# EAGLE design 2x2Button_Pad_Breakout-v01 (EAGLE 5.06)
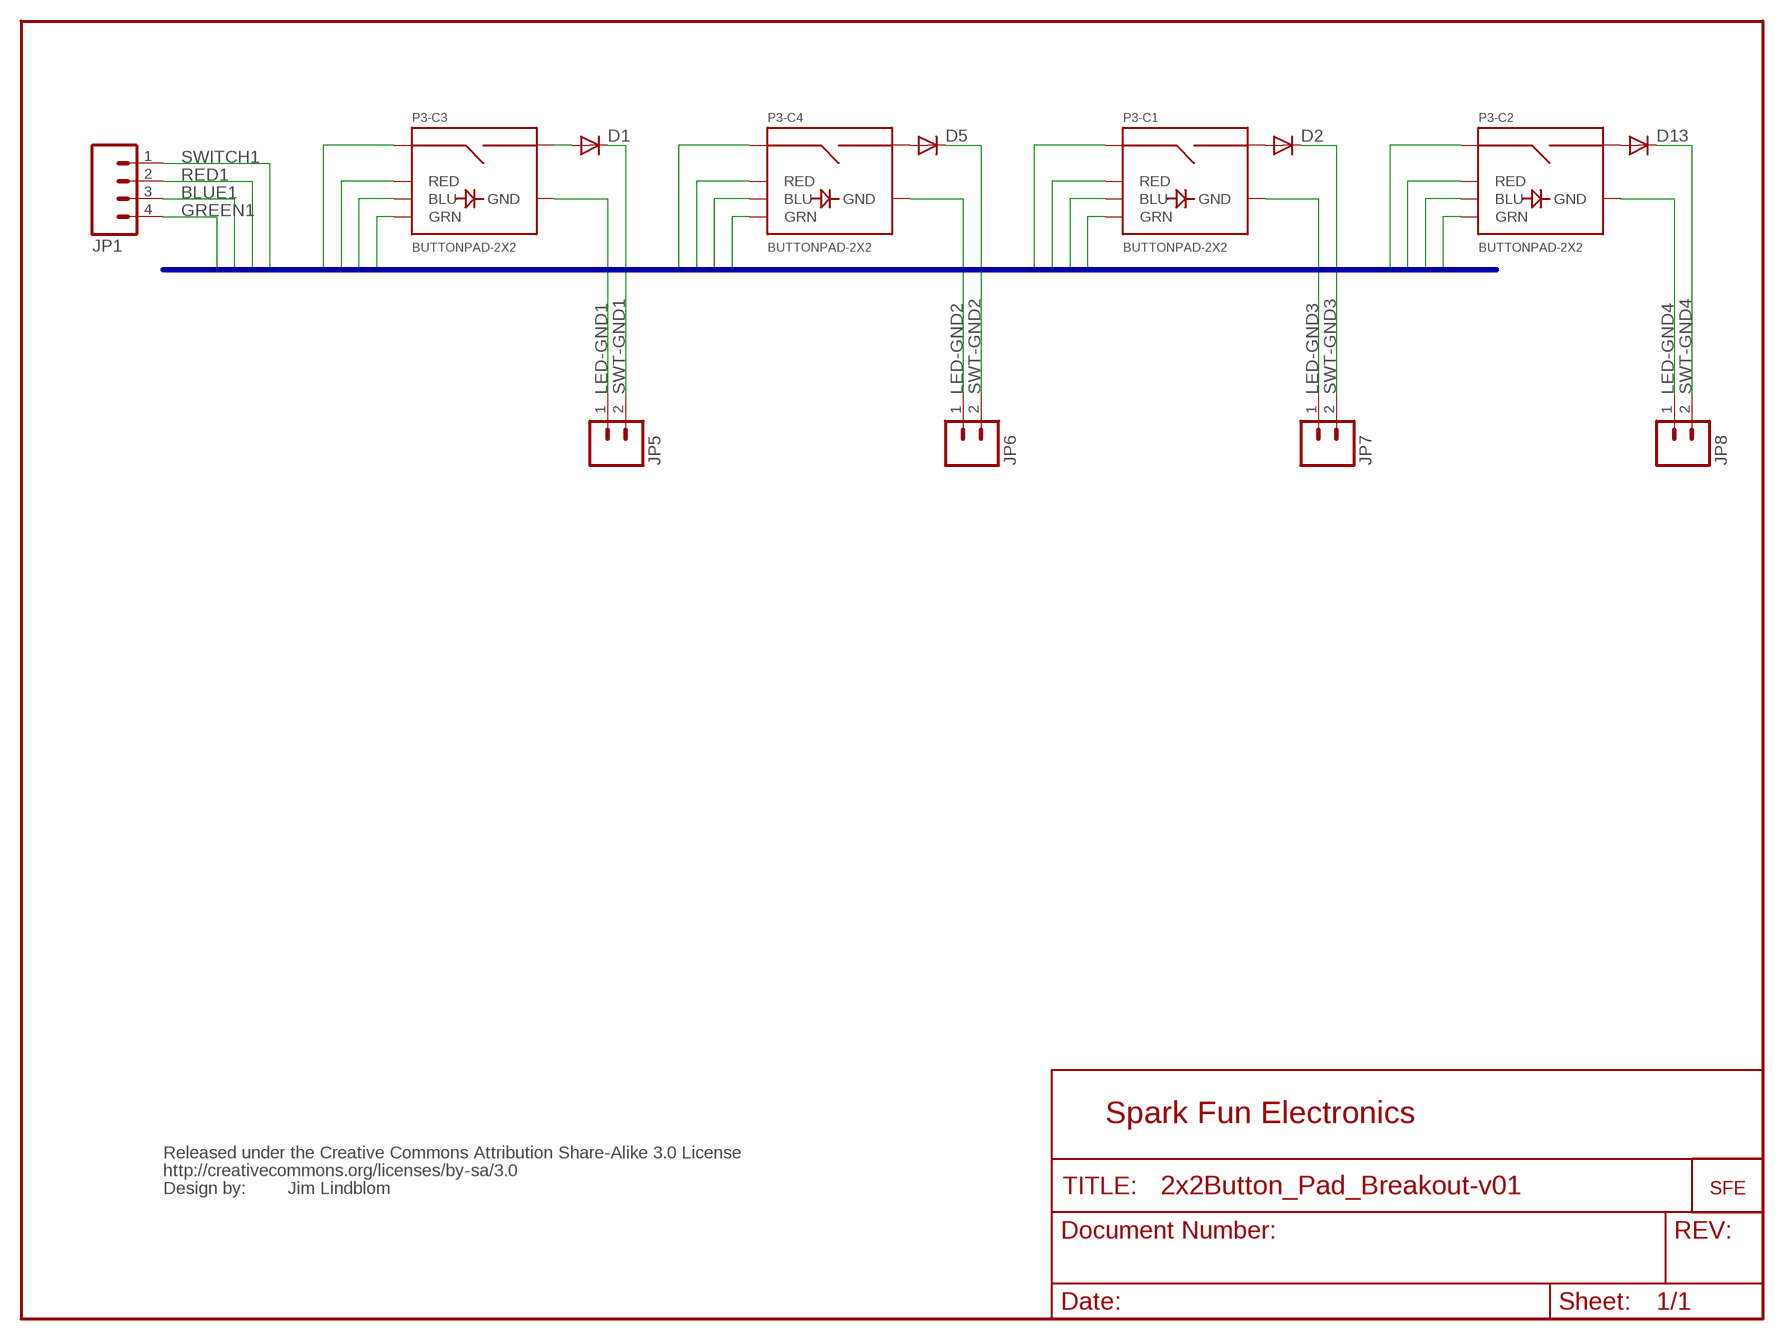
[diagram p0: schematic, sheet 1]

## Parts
D1  DIODE-1N4148  [DOIDE-1N4148]
D2  DIODE-1N4148  [DOIDE-1N4148]
D5  DIODE-1N4148  [DOIDE-1N4148]
D13  DIODE-1N4148  [DOIDE-1N4148]
JP1  M04POLAR  [MOLEX-1X4]
JP5  M02POLAR  [MOLEX-1X2]
JP6  M02POLAR  [MOLEX-1X2]
JP7  M02POLAR  [MOLEX-1X2]
JP8  M02POLAR  [MOLEX-1X2]
P3  BUTTONPAD-2X2  [BUTTONPAD-2X2]
U$1  LOGO-SFENEW  [SFE-NEW-WEBLOGO]
U$2  CREATIVE_COMMONS  [CREATIVE_COMMONS]

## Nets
BLUE1 [LEDPower]: JP1.3 P3.BLU1(-C1:BLU) P3.BLU2(-C2:BLU) P3.BLU3(-C3:BLU) P3.BLU4(-C4:BLU)
GREEN1 [LEDPower]: JP1.4 P3.GRN1(-C1:GRN) P3.GRN2(-C2:GRN) P3.GRN3(-C3:GRN) P3.GRN4(-C4:GRN)
LED-GND1 [LEDPower]: JP5.1 P3.GND3(-C3:GND)
LED-GND2 [LEDPower]: JP6.1 P3.GND4(-C4:GND)
LED-GND3 [LEDPower]: JP7.1 P3.GND1(-C1:GND)
LED-GND4 [LEDPower]: JP8.1 P3.GND2(-C2:GND)
N$1: D1.P$1(A) P3.SIG6(-C3:SIG2)
N$2: D2.P$1(A) P3.SIG2(-C1:SIG2)
N$3: D13.P$1(A) P3.SIG4(-C2:SIG2)
N$5: D5.P$1(A) P3.SIG8(-C4:SIG2)
RED1 [LEDPower]: JP1.2 P3.RED1(-C1:RED) P3.RED2(-C2:RED) P3.RED3(-C3:RED) P3.RED4(-C4:RED)
SWITCH1 [ButtonSignal]: JP1.1 P3.SIG1(-C1:SIG1) P3.SIG3(-C2:SIG1) P3.SIG5(-C3:SIG1) P3.SIG7(-C4:SIG1)
SWT-GND1 [ButtonSignal]: D1.P$2(C) JP5.2
SWT-GND2 [ButtonSignal]: D5.P$2(C) JP6.2
SWT-GND3 [ButtonSignal]: D2.P$2(C) JP7.2
SWT-GND4 [ButtonSignal]: D13.P$2(C) JP8.2

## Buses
BUS1:RED1,BLUE1,GREEN1,SWITCH1

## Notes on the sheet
- Spark Fun Electronics
- Jim Lindblom

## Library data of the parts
D1 D2 D5 D13 = SparkFun:DIODE-1N4148
JP1 = SparkFun:M04: Header 4 Standard 4-pin 0.1" header. Use with straight break away headers (SKU : PRT-00116), right angle break away headers (PRT-00553), swiss pins (PRT-00743), machine pins (PRT-00117), and female headers (PRT-00115). Molex polarized connector foot print use with SKU : PRT-08231 with associated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
JP5-JP8 = SparkFun:M02: Header 2
P3 = SparkFun:BUTTONPAD-2X2: 5mm Button Pad Proven layout and schematic for 2x2 button pad. Panelize this device/fp to a 4x4 pad if needed. Spark Fun Electronics SKU : COM-07835. Compatible common cathode tri-color LED SKU : COM-00105
U$1 = SparkFun:LOGO-SFE: Spark Fun Electronics PCB Logo
U$2 = SparkFun:CREATIVE_COMMONS

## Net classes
0 Default: width 0.254 mm
1 Power: width 0.305 mm
2 LEDPower: width 0.305 mm
3 ButtonSignal: width 0.254 mm

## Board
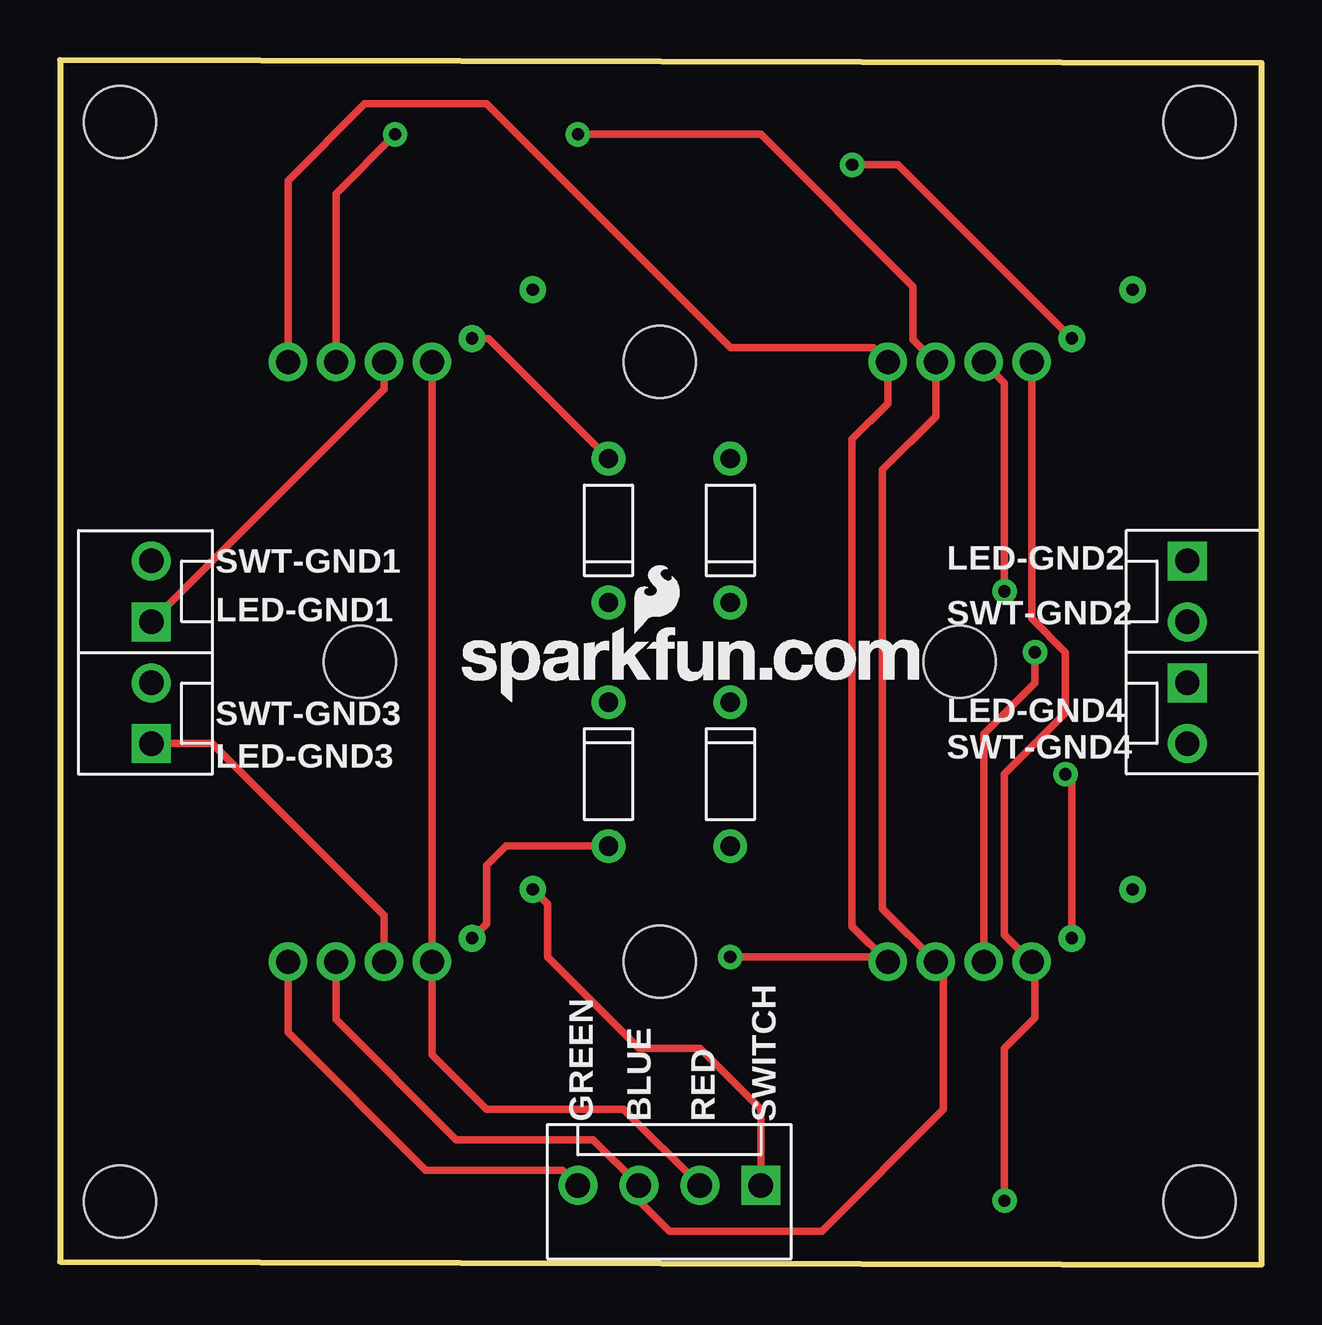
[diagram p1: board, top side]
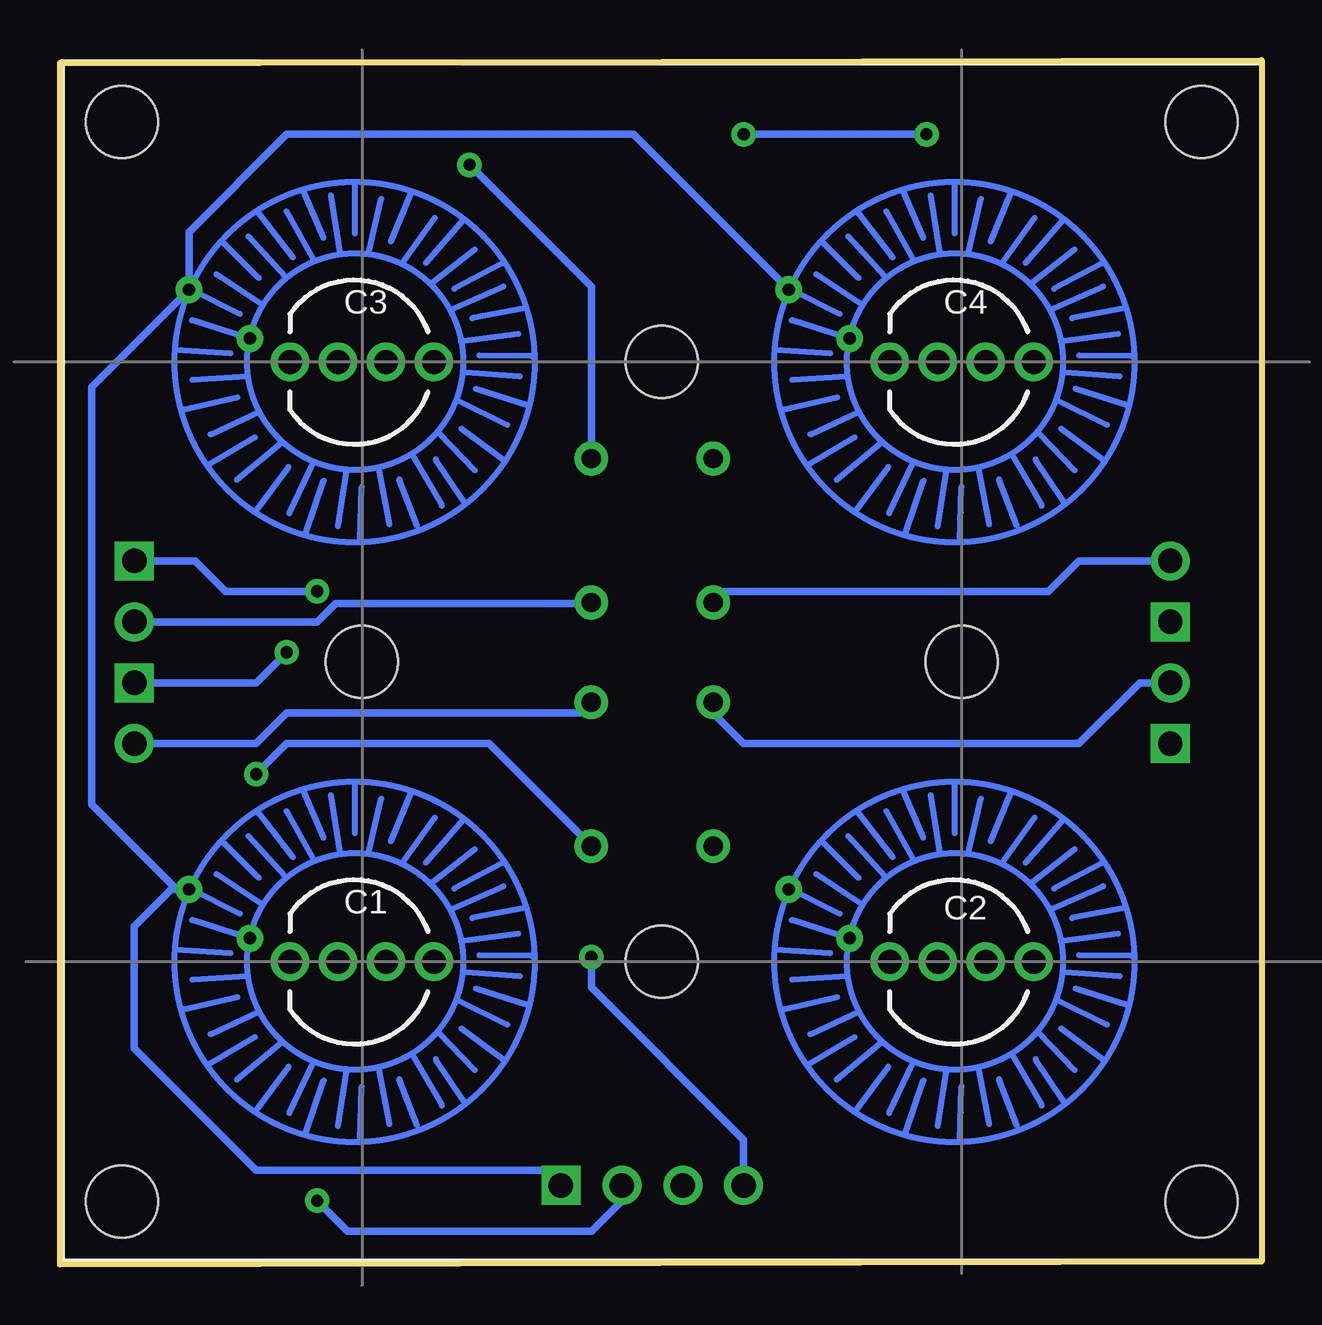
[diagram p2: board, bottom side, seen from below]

Size 50.09 x 50.22 mm. Coordinates in mm from the lower left corner, seen from the top.
Outline: 0,0.13 50.09,0 50.09,50.09 0,50.22 0,0.13
Copper layers (1*16): Top 0.035mm / dielectric 1.5mm / Bottom 0.035mm
Design rules "SparkFun": minimum track width 8mil, minimum drill 20mil, track to track 8mil, track to pad 8mil, pad to pad 8mil, via to via 8mil, smd to smd 8mil, copper to edge 10mil, drill to drill 8mil, minimum pad ring 12mil, minimum via ring 10mil, stop-mask expansion 4mil, vias tented up to drill 25mil, thermal gap 10mil

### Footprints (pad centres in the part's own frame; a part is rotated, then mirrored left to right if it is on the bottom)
DOIDE-1N4148 = drill 0.8 round: P$1 3,0; P$2 -3,0
MOLEX-1X4 = drill 1.016 square: 1 0,0 | drill 1.016 round: 2 2.54,0; 3 5.08,0; 4 7.62,0
MOLEX-1X2 = drill 1.016 square: 1 0,0 | drill 1.016 round: 2 2.54,0
BUTTONPAD-2X2 = drill 1 round: BLU1 13.5,12.5; BLU2 38.5,12.5; BLU3 13.5,37.5; BLU4 38.5,37.5; GND1 11.5,12.5; GND2 36.5,12.5; GND3 11.5,37.5; GND4 36.5,37.5; GRN1 15.5,12.5; GRN2 40.5,12.5; GRN3 15.5,37.5; GRN4 40.5,37.5; RED1 9.5,12.5; RED2 34.5,12.5; RED3 9.5,37.5; RED4 34.5,37.5 | drill 0.508 round: SIG1 5.288,15.513; SIG2 7.828,13.481; SIG3 30.288,15.513; SIG4 32.828,13.481; SIG5 5.288,40.513; SIG6 7.828,38.481; SIG7 30.288,40.513; SIG8 32.828,38.481 | hole 3: 12.5,25; 25,37.5; 37.5,25; 25,12.5; 2.5,2.5; 2.5,47.5; 47.5,47.5; 47.5,2.5

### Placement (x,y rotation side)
D1  27.94,30.61 90 top
D2  27.94,20.45 270 top
D5  22.86,30.61 90 top
D13  22.86,20.45 270 top
JP1  29.21,3.3 180 top
JP5  46.99,29.34 270 top
JP6  3.81,26.8 90 top
JP7  46.99,24.26 270 top
JP8  3.81,21.72 90 top
P3  50,0.13 0 bottom
U$1  16.75,23.45 0 top
U$2  not placed on the board

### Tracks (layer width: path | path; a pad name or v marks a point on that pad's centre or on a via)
BLUE1  (via drill 0.51)
  Top 0.305: P3.BLU2 11.5,10.22 16.51,5.21 22.23,5.21 JP1.3 24.13,2.67 25.4,1.4 31.75,1.4 36.83,6.48 36.83,12.3 P3.BLU1 34.29,14.84 34.29,33.15 36.5,35.36 P3.BLU3 35.56,38.57 35.56,40.77 29.21,47.12 v21.59,47.12 | P3.BLU4 11.5,44.65 v13.97,47.12
  Bottom 0.305: v13.97,47.12 v21.59,47.12
GREEN1  (via drill 0.51)
  Top 0.305: P3.GRN2 9.5,9.68 15.24,3.94 20.95,3.94 JP1.4 | v27.94,12.83 34.3,12.83 P3.GRN1 33.02,14.11 33.02,34.42 34.5,35.9 P3.GRN3 33.9,38.23 27.94,38.23 17.78,48.39 12.7,48.39 9.5,45.19 P3.GRN4
  Bottom 0.305: v27.94,12.83 27.94,11.56 21.59,5.21 JP1.4
LED-GND1  (via drill 0.51)
  Top 0.305: v39.37,28.07 39.37,36.76 P3.GND3
  Bottom 0.305: v39.37,28.07 43.18,28.07 44.45,29.34 JP5.1
LED-GND2
  Top 0.305: P3.GND4 13.5,36.49 JP6.1
LED-GND3  (via drill 0.51)
  Top 0.305: P3.GND1 38.5,22.12 40.64,24.26 v40.64,25.53
  Bottom 0.305: JP7.1 41.91,24.26 v40.64,25.53
LED-GND4
  Top 0.305: P3.GND2 13.5,14.57 6.35,21.72 JP8.1
N$1  (via drill 0.51)
  Top 0.305: v33.02,45.85 34.93,45.85 P3.SIG6
  Bottom 0.305: D1.P$1 27.94,40.77 v33.02,45.85
N$2  (via drill 0.51)
  Top 0.305: P3.SIG2 42.17,20.18 v41.91,20.45
  Bottom 0.305: v41.91,20.45 40.64,21.72 32.21,21.72 D2.P$1
N$3
  Top 0.305: D13.P$1 18.59,17.45 17.78,16.64 17.78,14.22 P3.SIG4
N$5
  Top 0.305: P3.SIG8 17.86,38.61 D5.P$1
RED1  (via drill 0.51)
  Top 0.305: JP1.2 23.5,6.48 17.78,6.48 15.5,8.76 P3.RED2 P3.RED4 | v39.37,2.67 39.37,9.02 40.64,10.29 40.64,12.49 P3.RED1 39.37,13.76 39.37,20.45 41.91,22.99 41.91,25.53 40.5,26.94 P3.RED3
  Bottom 0.305: JP1.2 26.67,2.67 27.94,1.4 38.1,1.4 v39.37,2.67
SWITCH1
  Top 0.305: JP1.1 29.21,6.48 26.67,9.02 24.13,9.02 20.32,12.83 20.32,15.03 P3.SIG3
  Bottom 0.305: JP1.1 29.84,3.94 41.91,3.94 46.99,9.02 46.99,14.1 45.45,15.64 P3.SIG1 45.23,15.64 48.77,19.18 48.77,36.58 P3.SIG5 44.71,43.05 40.64,47.12 26.19,47.12 P3.SIG7
SWT-GND1
  Bottom 0.305: JP5.2 39.37,26.8 38.61,27.56 27.99,27.56 D1.P$2
SWT-GND2
  Bottom 0.305: JP6.2 7.62,29.34 8.89,28.07 22.4,28.07 D5.P$2
SWT-GND3
  Bottom 0.305: JP7.2 41.91,21.72 40.64,22.99 28.4,22.99 D2.P$2
SWT-GND4
  Bottom 0.305: D13.P$2 22.86,22.99 21.59,21.72 7.62,21.72 5.08,24.26 JP8.2

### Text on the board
tPlace: SWT-GND1 | LED-GND2 | LED-GND1 | SWT-GND2 | SWT-GND3 | LED-GND4 | LED-GND3 | SWT-GND4 | GREEN | BLUE | RED | SWITCH
Document: N. Seidle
